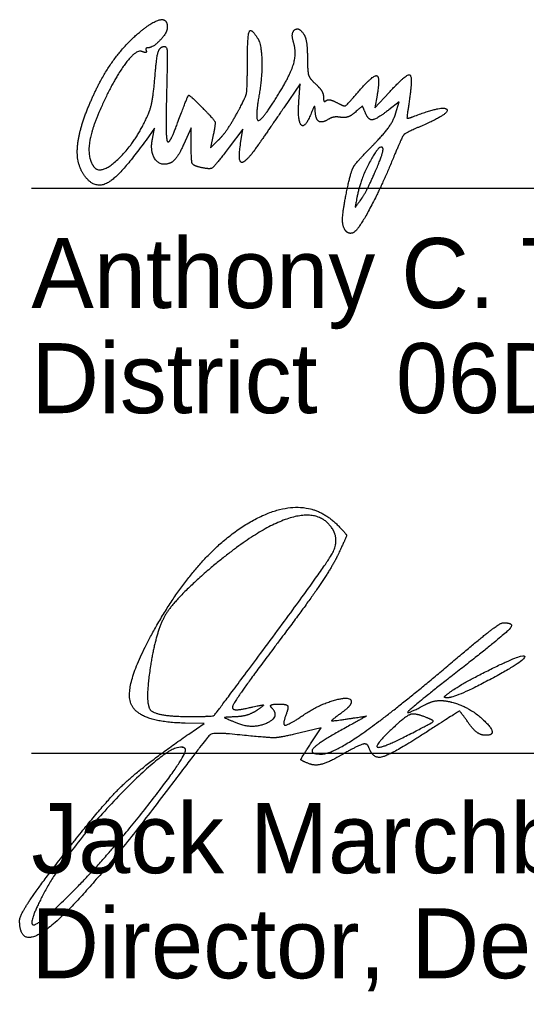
# Model space of a CAD drawing. Extents: x 0 to 34, y 0 to 22.
# Drawn here: x 24.504 to 25.517, y 3.449 to 5.408 of the extents above; entities that cross this region are included whole.
import ezdxf

# ---------------------------------------------------------------- set-up
doc = ezdxf.new("R2010")
doc.units = 0
doc.layers.add('SH_Data', color=7, linetype='Continuous')
doc.layers.add('SH_Text', color=7, linetype='Continuous')

msp = doc.modelspace()

# ---------------------------------------------------------------- linework, layer by layer
at = {"layer": 'SH_Data'}
for p, q in [((24.5279, 5.071), (28.0279, 5.071)), ((24.5279, 3.9416), (28.0279, 3.9416))]:
    msp.add_line(p, q, dxfattribs=at)
at = {"layer": 'SH_Text'}
for p, q in [((25.2156, 5.1053), (25.2156, 5.1053)), ((25.157, 4.9842), (25.157, 4.9842)), ((24.9902, 4.1466), (24.9902, 4.1466)), ((25.3555, 4.0567), (25.3555, 4.0567)), ((25.3107, 4.0151), (25.3107, 4.0151))]:
    msp.add_line(p, q, dxfattribs=at)
for points in [[(25.0623, 5.2437), (25.0648, 5.2791), (25.032, 5.2311)], [(25.2187, 5.2567), (25.2144, 5.2311), (25.2425, 5.2618)], [(25.2556, 5.2194), (25.2625, 5.2434), (25.2419, 5.2272)], [(24.7697, 5.1686), (24.774, 5.1907), (24.757, 5.1669)], [(24.8473, 5.154), (24.8471, 5.1911), (24.8322, 5.1583)], [(24.8914, 5.1773), (24.8859, 5.1511), (24.902, 5.1671)], [(24.946, 5.1597), (24.9507, 5.1883), (24.9233, 5.1524)], [(24.8425, 3.9797), (24.8732, 4.0009), (24.8354, 4.0015)], [(25.0855, 3.9598), (25.1067, 3.9922), (25.0649, 3.9821)]]:
    msp.add_lwpolyline(points, dxfattribs=at)
for points in [[(24.7437, 5.382), (24.7705, 5.4046), (24.7995, 5.4099), (24.7995, 5.3923)], [(24.7995, 5.3923), (24.7995, 5.3817), (24.7707, 5.3511), (24.7606, 5.3511)], [(24.9595, 5.3186), (24.9595, 5.3745), (24.9665, 5.3921), (24.9801, 5.3701)], [(25.0516, 5.3628), (25.0458, 5.381), (25.0625, 5.3934), (25.0723, 5.3781)], [(24.6396, 5.2274), (24.6598, 5.2786), (24.7107, 5.3543), (24.7437, 5.382)], [(24.9801, 5.3701), (24.9876, 5.358), (24.9892, 5.2936), (24.983, 5.2576)], [(25.0723, 5.3781), (25.0761, 5.372), (25.0793, 5.3505), (25.0794, 5.3303)], [(24.7606, 5.3511), (24.7578, 5.3511), (24.7563, 5.3485), (24.7574, 5.3453)], [(24.775, 5.2944), (24.7778, 5.3297), (24.7833, 5.3511), (24.79, 5.3533)], [(24.79, 5.3533), (24.7983, 5.356), (24.7999, 5.337), (24.798, 5.2599)], [(25.015, 5.2476), (25.0431, 5.292), (25.0586, 5.3406), (25.0516, 5.3628)], [(24.7485, 5.3438), (24.7359, 5.3486), (24.6881, 5.2804), (24.6629, 5.2218)], [(24.7574, 5.3453), (24.7584, 5.3422), (24.7544, 5.3415), (24.7485, 5.3438)], [(25.0794, 5.3303), (25.0795, 5.3038), (25.084, 5.2895), (25.0955, 5.2791)], [(24.9388, 5.2206), (24.9559, 5.2516), (24.9595, 5.2686), (24.9595, 5.3186)], [(24.7618, 5.2191), (24.7666, 5.2301), (24.7725, 5.264), (24.775, 5.2944)], [(25.1806, 5.2627), (25.2101, 5.2967), (25.225, 5.2944), (25.2187, 5.2567)], [(25.2425, 5.2618), (25.2773, 5.3), (25.2902, 5.2946), (25.2828, 5.2451)], [(25.0955, 5.2791), (25.1043, 5.2711), (25.1115, 5.2591), (25.1115, 5.2525)], [(24.798, 5.2599), (24.7966, 5.2066), (24.7979, 5.163), (24.8008, 5.163)], [(24.8201, 5.2011), (24.8401, 5.2554), (24.8441, 5.2575), (24.8721, 5.2289)], [(24.983, 5.2576), (24.9743, 5.2081), (24.9874, 5.204), (25.015, 5.2476)], [(25.1115, 5.2525), (25.1115, 5.2458), (25.1138, 5.2427), (25.1165, 5.2454)], [(25.1382, 5.2416), (25.1526, 5.2339), (25.1582, 5.2367), (25.1806, 5.2627)], [(24.8721, 5.2289), (24.8933, 5.2073), (24.8961, 5.1997), (24.8914, 5.1773)], [(25.032, 5.2311), (25.0139, 5.2047), (24.9911, 5.1715), (24.9813, 5.1574)], [(25.087, 5.2204), (25.0747, 5.1897), (25.0596, 5.204), (25.0623, 5.2437)], [(25.095, 5.2255), (25.0946, 5.235), (25.0922, 5.2335), (25.087, 5.2204)], [(25.1165, 5.2454), (25.1193, 5.2482), (25.1291, 5.2465), (25.1382, 5.2416)], [(25.1942, 5.2234), (25.19, 5.2344), (25.188, 5.2344), (25.1752, 5.2228)], [(25.2828, 5.2451), (25.2779, 5.2125), (25.2788, 5.2091), (25.2911, 5.2138)], [(25.2911, 5.2138), (25.3506, 5.2367), (25.365, 5.2197), (25.3071, 5.1949)], [(24.6342, 5.0954), (24.6185, 5.1169), (24.6211, 5.1804), (24.6396, 5.2274)], [(24.6629, 5.2218), (24.6464, 5.1833), (24.6408, 5.1324), (24.6511, 5.1157)], [(24.6511, 5.1157), (24.6644, 5.0942), (24.7369, 5.1619), (24.7618, 5.2191)], [(24.902, 5.1671), (24.9109, 5.1759), (24.9275, 5.2), (24.9388, 5.2206)], [(25.1215, 5.2084), (25.1084, 5.2002), (25.0956, 5.2085), (25.095, 5.2255)], [(25.1462, 5.2122), (25.1381, 5.2136), (25.127, 5.2118), (25.1215, 5.2084)], [(25.1752, 5.2228), (25.1673, 5.2157), (25.1542, 5.2109), (25.1462, 5.2122)], [(25.2419, 5.2272), (25.2173, 5.2079), (25.2007, 5.2066), (25.1942, 5.2234)], [(25.2086, 5.1547), (25.2307, 5.1771), (25.2518, 5.2062), (25.2556, 5.2194)], [(24.8008, 5.163), (24.8038, 5.1631), (24.8125, 5.1802), (24.8201, 5.2011)], [(25.3071, 5.1949), (25.2757, 5.1814), (25.2684, 5.1736), (25.2535, 5.1372)], [(24.757, 5.1669), (24.7073, 5.0971), (24.6552, 5.0667), (24.6342, 5.0954)], [(24.8052, 5.1208), (24.7863, 5.1136), (24.7648, 5.1427), (24.7697, 5.1686)], [(24.8322, 5.1583), (24.8241, 5.1402), (24.8119, 5.1234), (24.8052, 5.1208)], [(24.8615, 5.1133), (24.8507, 5.1161), (24.8474, 5.1255), (24.8473, 5.154)], [(24.9233, 5.1524), (24.894, 5.1141), (24.8837, 5.1075), (24.8615, 5.1133)], [(24.9813, 5.1574), (24.9565, 5.1216), (24.94, 5.1227), (24.946, 5.1597)], [(25.16, 5.0741), (25.1667, 5.1053), (25.1773, 5.1229), (25.2086, 5.1547)], [(25.2295, 5.1517), (25.2229, 5.1583), (25.1859, 5.0896), (25.1798, 5.0591)], [(25.2156, 5.1053), (25.2255, 5.1285), (25.2318, 5.1494), (25.2295, 5.1517)], [(25.2535, 5.1372), (25.2283, 5.0755), (25.1799, 4.9845), (25.1705, 4.9814)], [(25.1858, 5.0471), (25.1922, 5.0559), (25.2056, 5.0821), (25.2156, 5.1053)], [(25.157, 4.9842), (25.149, 4.9922), (25.1502, 5.0284), (25.16, 5.0741)], [(25.1798, 5.0591), (25.1745, 5.0331), (25.175, 5.0322), (25.1858, 5.0471)], [(25.1705, 4.9814), (25.1661, 4.9799), (25.16, 4.9812), (25.157, 4.9842)], [(24.7789, 4.1974), (24.8651, 4.3477), (25.0732, 4.4638), (25.1389, 4.3981)], [(25.1299, 4.3889), (25.104, 4.4309), (24.9779, 4.3898), (24.8825, 4.3082)], [(24.9902, 4.1466), (25.1115, 4.3101), (25.144, 4.3663), (25.1299, 4.3889)], [(25.1389, 4.3981), (25.1577, 4.3793), (25.1577, 4.3743), (25.1394, 4.3359)], [(25.1394, 4.3359), (25.1284, 4.3129), (25.0767, 4.2373), (25.0245, 4.168)], [(24.8825, 4.3082), (24.8159, 4.2511), (24.7771, 4.187), (24.766, 4.1158)], [(24.8354, 4.0015), (24.7375, 4.0032), (24.7141, 4.0844), (24.7789, 4.1974)], [(25.369, 4.1239), (25.4194, 4.1667), (25.4649, 4.2019), (25.4701, 4.202)], [(25.4701, 4.202), (25.495, 4.2025), (25.4716, 4.1769), (25.3857, 4.1097)], [(25.0245, 4.168), (24.9722, 4.0986), (24.9295, 4.0379), (24.9295, 4.0332)], [(24.844, 4.0147), (24.8907, 4.0147), (24.8953, 4.0188), (24.9902, 4.1466)], [(25.3555, 4.0567), (25.3759, 4.0746), (25.5079, 4.1404), (25.5131, 4.1352)], [(25.5131, 4.1352), (25.5193, 4.1291), (25.3767, 4.0522), (25.359, 4.0522)], [(24.766, 4.1158), (24.7545, 4.0424), (24.776, 4.0147), (24.844, 4.0147)], [(25.1076, 3.9397), (25.1307, 3.9397), (25.2567, 4.0285), (25.369, 4.1239)], [(25.3857, 4.1097), (25.2925, 4.0367), (25.271, 4.0151), (25.315, 4.0386)], [(25.359, 4.0522), (25.3542, 4.0522), (25.3526, 4.0542), (25.3555, 4.0567)], [(24.9638, 4.0325), (24.9894, 4.0384), (24.9934, 4.0372), (24.9795, 4.0278)], [(25.0086, 4.0314), (25.004, 4.036), (25.0103, 4.0397), (25.0225, 4.0397)], [(25.0225, 4.0397), (25.037, 4.0397), (25.0422, 4.0333), (25.0375, 4.0209)], [(25.0736, 4.0191), (25.1025, 4.0389), (25.167, 4.0564), (25.167, 4.0444)], [(25.167, 4.0444), (25.167, 4.0399), (25.1572, 4.0291), (25.1453, 4.0204)], [(25.315, 4.0386), (25.3276, 4.0454), (25.3515, 4.0475), (25.3681, 4.0433)], [(25.3681, 4.0433), (25.4042, 4.0341), (25.4625, 3.9772), (25.4358, 3.9772)], [(24.9295, 4.0332), (24.9295, 4.0284), (24.9449, 4.0281), (24.9638, 4.0325)], [(24.9795, 4.0278), (24.9692, 4.0208), (24.9495, 4.0146), (24.9357, 4.0141)], [(24.9399, 4.0014), (24.9698, 3.9894), (25.026, 4.014), (25.0086, 4.0314)], [(25.0375, 4.0209), (25.0285, 3.9977), (25.0414, 3.997), (25.0736, 4.0191)], [(25.1453, 4.0204), (25.1264, 4.0066), (25.1284, 4.0053), (25.161, 4.0102)], [(25.161, 4.0102), (25.1977, 4.0157), (25.1976, 4.0155), (25.1522, 3.9904)], [(25.3107, 4.0151), (25.2935, 4.0214), (25.277, 4.0163), (25.2576, 3.9986)], [(25.2826, 3.9788), (25.329, 4.0025), (25.3325, 4.0071), (25.3107, 4.0151)], [(25.4011, 4.0019), (25.3843, 4.0259), (25.3822, 4.0255), (25.3165, 3.9831)], [(24.9357, 4.0141), (24.9133, 4.0132), (24.9138, 4.0119), (24.9399, 4.0014)], [(25.2576, 3.9986), (25.2133, 3.9581), (25.2246, 3.9492), (25.2826, 3.9788)], [(25.4358, 3.9772), (25.4262, 3.9772), (25.4106, 3.9883), (25.4011, 4.0019)], [(24.5916, 3.7375), (24.6692, 3.8379), (24.7493, 3.9152), (24.8425, 3.9797)], [(24.9237, 3.9798), (24.8903, 3.9831), (24.8786, 3.9726), (24.8019, 3.8709)], [(25.0649, 3.9821), (25.0246, 3.9723), (25.0023, 3.972), (24.9237, 3.9798)], [(25.1522, 3.9904), (25.1011, 3.9622), (25.0814, 3.9397), (25.1076, 3.9397)], [(25.3165, 3.9831), (25.2476, 3.9387), (25.2101, 3.929), (25.202, 3.9534)], [(25.0843, 3.9198), (25.0661, 3.9267), (25.0662, 3.9304), (25.0855, 3.9598)], [(25.202, 3.9534), (25.1991, 3.9619), (25.1799, 3.9567), (25.1508, 3.9396)], [(24.8354, 3.9504), (24.8145, 3.9713), (24.596, 3.7457), (24.5497, 3.6553)], [(24.6198, 3.6741), (24.6874, 3.7431), (24.8431, 3.9427), (24.8354, 3.9504)], [(25.1508, 3.9396), (25.1252, 3.9245), (25.0953, 3.9155), (25.0843, 3.9198)], [(24.8019, 3.8709), (24.6496, 3.6689), (24.5045, 3.5402), (24.5045, 3.6072)], [(24.5045, 3.6072), (24.5045, 3.6168), (24.5437, 3.6755), (24.5916, 3.7375)], [(24.5497, 3.6553), (24.5184, 3.5944), (24.55, 3.6028), (24.6198, 3.6741)]]:
    msp.add_open_spline(points, degree=2, dxfattribs=at)

# ---------------------------------------------------------------- texts
for s, p in [('Anthony C. Turowski, P.E.', (24.5279, 4.831)), ('District       Deputy Director', (24.5279, 4.621)), ('              06', (24.5279, 4.621)), ('Jack Marchbanks, PhD', (24.5279, 3.7016)), ('Director, Department of Transportation', (24.5279, 3.4916))]:
    msp.add_text(s, height=0.14, dxfattribs=at).set_placement(p)

doc.saveas('drawing.dxf')
